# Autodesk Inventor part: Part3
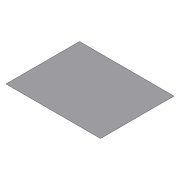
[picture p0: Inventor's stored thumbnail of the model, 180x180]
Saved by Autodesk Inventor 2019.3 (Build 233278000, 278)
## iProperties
Created: 2019-01
Part Number: Part3
Material: GFRC
Document SubType Name: Modeling
Designer: m.vorobev
Density: 1.7 g/cm^3
Appearance: Plate
Author: m.vorobev
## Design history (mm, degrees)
sketch "Sketch1"
  geometry: L1 (6211.022, -4831.411)-(-6211.022, -4831.411); L2 (-6211.022, -4831.411)-(-6211.022, 4831.411); L3 (-6211.022, 4831.411)-(6211.022, 4831.411); L4 (6211.022, 4831.411)-(6211.022, -4831.411); L5 (6211.022, -4831.411)-(-6211.022, 4831.411); L6 (-6211.022, -4831.411)-(6211.022, 4831.411); 1 further point
  constraints: 12 end point, 2 midpoint, 2 parallel, 1 horizontal, 1 perpendicular
extrude "Extrusion1" new body sketch "Sketch1" distance "d0" = 1; taper "d1" = 0 deg
body "Solid1"
